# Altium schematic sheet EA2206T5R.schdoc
size 127 x 101 mm
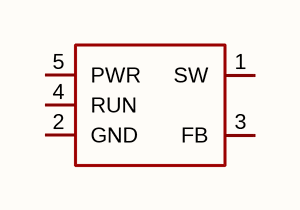
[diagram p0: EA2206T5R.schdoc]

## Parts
U?  ea2206t5r  [SOT-23-5_L3.0-W1.5-P0.95-LS2.8-BL]  (value not drawn)

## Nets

Not connected (* = marked no-connect by the designer): U? 1(SW) 2(GND) 3(FB) 4(RUN) 5(PWR)

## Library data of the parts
U? = ea2206t5r: 功能类型:升压型;工作电压:2.5V~5.5V;输出电压:-;输出电流:-;输出类型:可调;; Manufacturer: everanalog(申风); AddInBom: yes; ModelId: 424d41c645fb4cc2a3598f66fad27964; ModelTransform: 118.11,110.236,0,0,0,0,0,0,0; Function: 升压型; Frequency - Switching: 1.2MHz; Number of Outputs: 1; Topology: 升压式; Quiescent Current: 40uA; Switch tube (built-in/external): 内置; Output Type: 可调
